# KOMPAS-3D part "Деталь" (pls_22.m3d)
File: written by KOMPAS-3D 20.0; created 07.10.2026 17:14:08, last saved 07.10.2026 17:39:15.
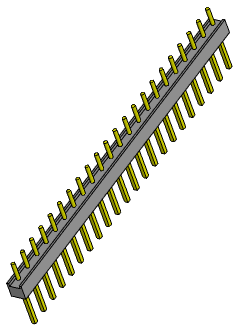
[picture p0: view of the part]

Document properties: Полное имя файла: D:\myProjects\Progect_esp32\box_compas\pls_22.m3d

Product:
- Part/product: Деталь
    Масса: 0.00286774

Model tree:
1. Эскиз:1
2. Элемент выдавливания:1
     Расстояние 1 = 2.5
3. Эскиз:2  (with: Элемент выдавливания:1)
4. Элемент выдавливания:2
     Расстояние 1 = 6
5. Массив по сетке:1  (with: Элемент выдавливания:2, Эскиз:2)  (22 pattern instances)
     Шаг 1 = 2.54; Угол раствора = 90
6. Эскиз:3  (with: Элемент выдавливания:1)
7. Элемент выдавливания:3
     Расстояние 1 = 3
8. Массив по сетке:2  (with: Элемент выдавливания:3, Эскиз:3)  (22 pattern instances)
     Шаг 1 = 2.54; Угол раствора = 90; Геометрический массив = 128
9. Эскиз:4  (with: Элемент выдавливания:1)
10. Элемент выдавливания:4
     Расстояние 2 = 55.88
